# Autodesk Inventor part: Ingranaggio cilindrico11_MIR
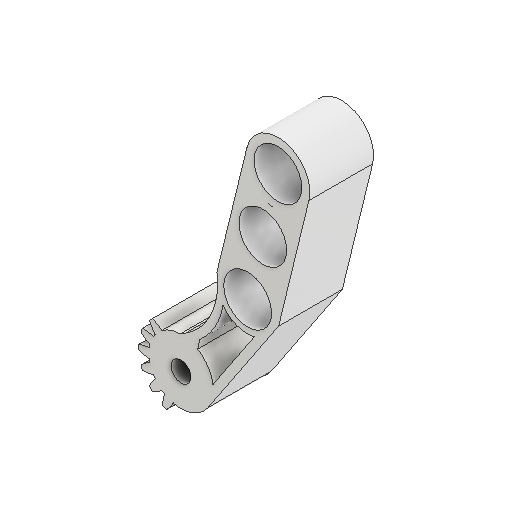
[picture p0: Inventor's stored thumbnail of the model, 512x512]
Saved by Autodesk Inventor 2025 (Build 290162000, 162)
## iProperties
Created: 2021-06
Part Number: Ingranaggio cilindrico11_MIR
Material: Plastica ABS
Document SubType Name: Modeling
Designer: Ryzen5700u
Density: 1.06 g/cm^3
Appearance: Default
Author: Ryzen5700u
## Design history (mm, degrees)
feature "Solido1"
node "Solido2"
